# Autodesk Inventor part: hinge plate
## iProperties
Thickness: 0.060 in
BendRadius: 0.060 in
Author: Tom Cross
Shininess: 20.0
PropertySet Name: _Private Model Information
Length Units: 11272
Angle Units: 11286
Time Units: 11279
Mass Units: 11290
Length Display Precision: 3
Angle Display Precision: 2
Compacted: True
Created: 2001-09
Part Number: hinge plate
Document SubType Name: Modeling
Designer: Tom Cross
Control State: 0
Master: False
Checked Out: False
PropertySet Name: Design Tracking Control
Density: 0.0
Volumn: 0.0
Area: 0.0
PropertySet Name: Model Information
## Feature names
1. Extrusion3
2. Extrusion4
3. Rectangular Pattern2
4. Plate1
